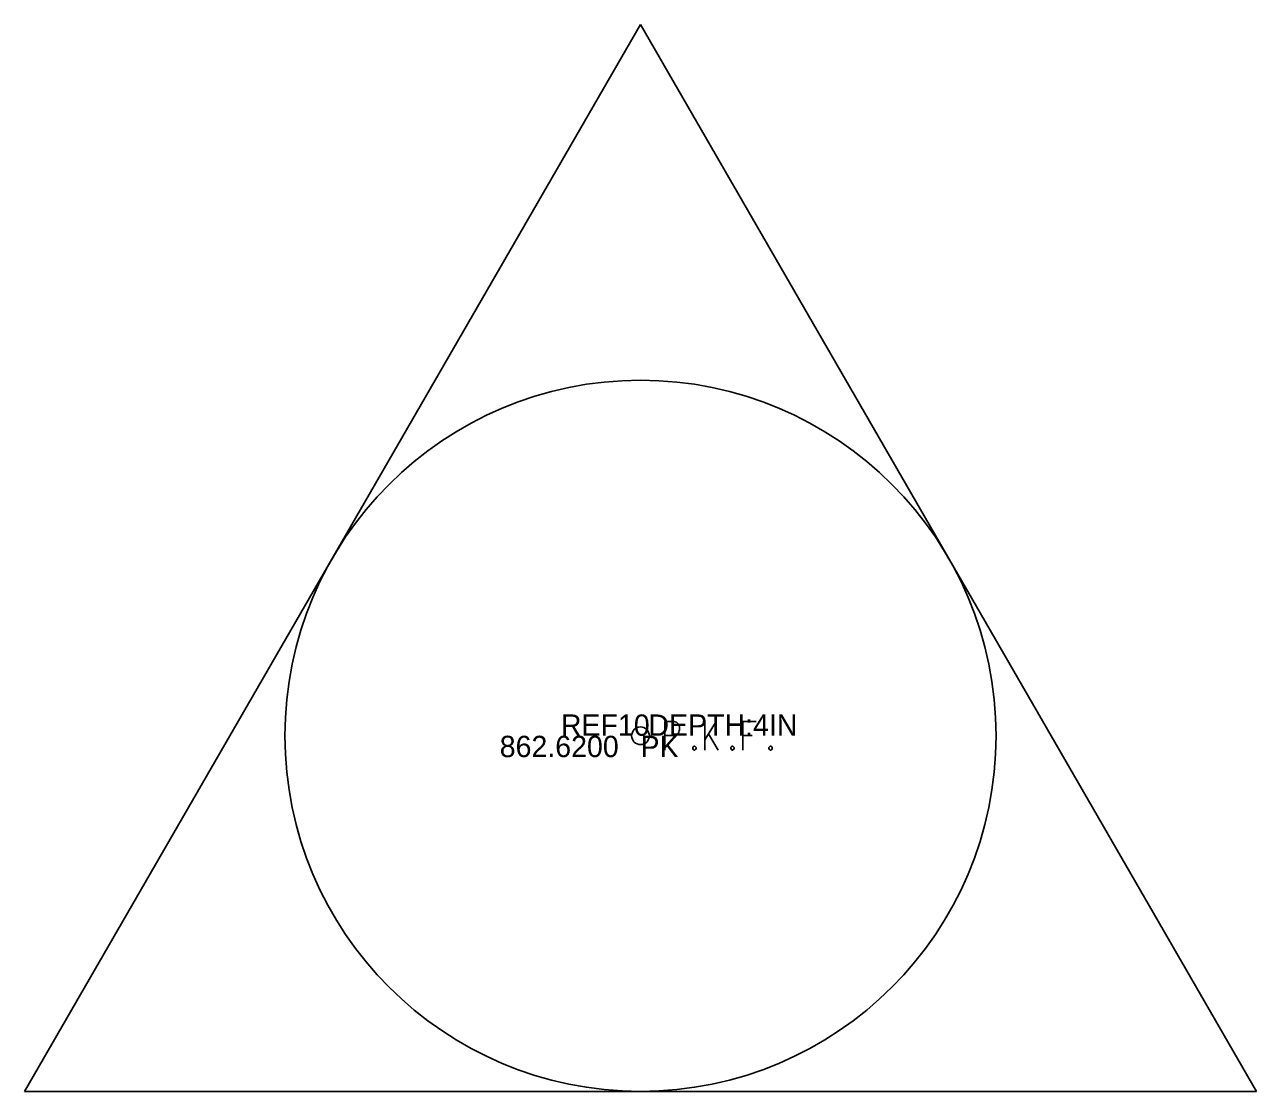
# Model space of a CAD drawing. Extents: x 1785178 to 1804417, y 483851 to 522189.
# Drawn here: x 1800358.173 to 1800361.637, y 494995.062 to 494998.062 of the extents above; entities that cross this region are included whole.
import ezdxf

# ---------------------------------------------------------------- set-up
doc = ezdxf.new("R2010")
doc.units = 0
for name, color, linetype in [('SV_Control_Point', 7, 'Continuous'), ('SV_X_Control_Cells_Found', 7, 'Continuous'), ('SV_X_Text_Comment', 7, 'Continuous'), ('SV_X_Text_Description', 7, 'Continuous'), ('SV_X_Text_Elevation', 7, 'Continuous'), ('SV_X_Text_Name', 7, 'Continuous')]:
    doc.layers.add(name, color=color, linetype=linetype)

msp = doc.modelspace()

# ---------------------------------------------------------------- linework, layer by layer
at = {"layer": 'SV_Control_Point'}
for p, q in [((1800358.1729, 494995.0622), (1800359.905, 494998.0622)), ((1800359.905, 494998.0622), (1800361.6371, 494995.0622)), ((1800359.905, 494996.0622), (1800359.905, 494996.0622)), ((1800361.6371, 494995.0622), (1800358.1729, 494995.0622))]:
    msp.add_line(p, q, dxfattribs=at)
msp.add_circle((1800359.905, 494996.0622), 1, dxfattribs=at)
at = {"layer": 'SV_X_Control_Cells_Found'}
for points in [[(1800359.9731, 494996.0222), (1800359.9731, 494996.1022), (1800359.9995, 494996.1022), (1800360.0023, 494996.1015), (1800360.0061, 494996.1003), (1800360.0078, 494996.099), (1800360.0094, 494996.0978), (1800360.0116, 494996.0946), (1800360.0133, 494996.0915), (1800360.0144, 494996.0864), (1800360.0144, 494996.0789), (1800360.0139, 494996.0764), (1800360.0128, 494996.0726), (1800360.0105, 494996.0682), (1800360.0083, 494996.0663), (1800360.0067, 494996.065), (1800360.0039, 494996.0638), (1800359.9995, 494996.0631), (1800359.9731, 494996.0631)], [(1800360.0855, 494996.1022), (1800360.0855, 494996.0222)], [(1800360.1175, 494996.1022), (1800360.0855, 494996.0512)], [(1800360.2305, 494996.1022), (1800360.1924, 494996.1022), (1800360.1924, 494996.0222)], [(1800360.096, 494996.0675), (1800360.123, 494996.0222)], [(1800360.1924, 494996.0631), (1800360.2194, 494996.0631)], [(1800360.0552, 494996.0329), (1800360.0579, 494996.0329), (1800360.0596, 494996.0316), (1800360.0613, 494996.0291), (1800360.0613, 494996.026), (1800360.0596, 494996.0234), (1800360.0579, 494996.0222), (1800360.0552, 494996.0222), (1800360.0535, 494996.0234), (1800360.0519, 494996.026), (1800360.0519, 494996.0291), (1800360.0535, 494996.0316), (1800360.0552, 494996.0329)], [(1800360.1621, 494996.0329), (1800360.1649, 494996.0329), (1800360.1665, 494996.0316), (1800360.1682, 494996.0291), (1800360.1682, 494996.026), (1800360.1665, 494996.0234), (1800360.1649, 494996.0222), (1800360.1621, 494996.0222), (1800360.1605, 494996.0234), (1800360.1588, 494996.026), (1800360.1588, 494996.0291), (1800360.1605, 494996.0316), (1800360.1621, 494996.0329)], [(1800360.2696, 494996.0329), (1800360.2723, 494996.0329), (1800360.274, 494996.0316), (1800360.2756, 494996.0291), (1800360.2756, 494996.026), (1800360.274, 494996.0234), (1800360.2723, 494996.0222), (1800360.2696, 494996.0222), (1800360.2679, 494996.0234), (1800360.2663, 494996.026), (1800360.2663, 494996.0291), (1800360.2679, 494996.0316), (1800360.2696, 494996.0329)]]:
    msp.add_lwpolyline(points, dxfattribs=at)
msp.add_circle((1800359.905, 494996.0622), 0.0249, dxfattribs=at)

# ---------------------------------------------------------------- texts
at = {"layer": 'SV_X_Text_Comment'}
msp.add_text('PK', height=0.06, dxfattribs=at).set_placement((1800359.905, 494996.0022))
at = {"layer": 'SV_X_Text_Description'}
msp.add_text(' DEPTH:4IN', height=0.06, dxfattribs=at).set_placement((1800359.905, 494996.0622))
at = {"layer": 'SV_X_Text_Elevation'}
msp.add_text('862.6200', height=0.06, dxfattribs=at).set_placement((1800359.5091, 494996.0022))
at = {"layer": 'SV_X_Text_Name'}
msp.add_text('REF10', height=0.06, dxfattribs=at).set_placement((1800359.6811, 494996.0622))

doc.saveas('drawing.dxf')
